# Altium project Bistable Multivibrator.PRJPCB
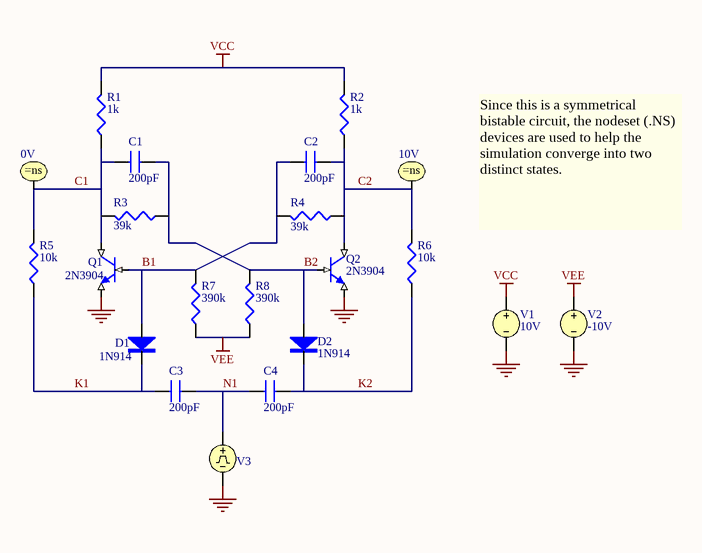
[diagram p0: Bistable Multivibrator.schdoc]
1 sheet, 21 parts. Net scope: global (net labels, ports and power ports of the same name join across sheets).

## Sheet Bistable Multivibrator.schdoc: Bistable Multivibrator
size A4; Organization: Altium Limited; Address1: L3, 12a Rodborough Rd; Address2: Frenchs Forest; Address3: NSW; Address4: Australia 2086; DocumentNumber: 1; SheetNumber: 1; SheetTotal: 1

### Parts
C1  200pF
C2  200pF
C3  200pF
C4  200pF
D1  1N914
D2  1N914
NS1  0V
NS2  10V
Q1  2N3904
Q2  2N3904
R1  1k
R2  1k
R3  39k
R4  39k
R5  10k
R6  10k
R7  390k
R8  390k
V1  10V
V2  -10V
V3  VPULSE  (value not drawn)

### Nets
GND: Q1.3(E) Q2.3(E) V1.2 V2.2 V3.2
VCC: R1.1(TOP) R2.1(TOP) V1.1
VEE: R7.2(BOT) R8.2(BOT) V2.1
B1: C2.1 D1.1(A) Q1.2(B) R4.1(TOP) R7.1(TOP)
B2: C1.2 D2.1(A) Q2.2(B) R3.2(BOT) R8.1(TOP)
C1: C1.1 NS1.1 Q1.1(C) R1.2(BOT) R3.1(TOP) R5.1(TOP)
C2: C2.2 NS2.1 Q2.1(C) R2.2(BOT) R4.2(BOT) R6.1(TOP)
K1: C3.1 D1.2(K) R5.2(BOT)
K2: C4.2 D2.2(K) R6.2(BOT)
N1: C3.2 C4.1 V3.1

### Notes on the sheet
- Since this is a symmetrical bistable circuit, the nodeset (.NS) devices are used to help the simulation converge into two distinct states.

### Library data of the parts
C1-C4 = CAP: Capacitor
D1 D2 = 1N914: Diode
NS1 NS2 = .NS: Node Set
Q1 Q2 = 2N3904: NPN BJT
R1-R8 = RES: Resistor
V1 V2 = VSRC: Voltage Source
V3 = VPULSE: Pulse Voltage Source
